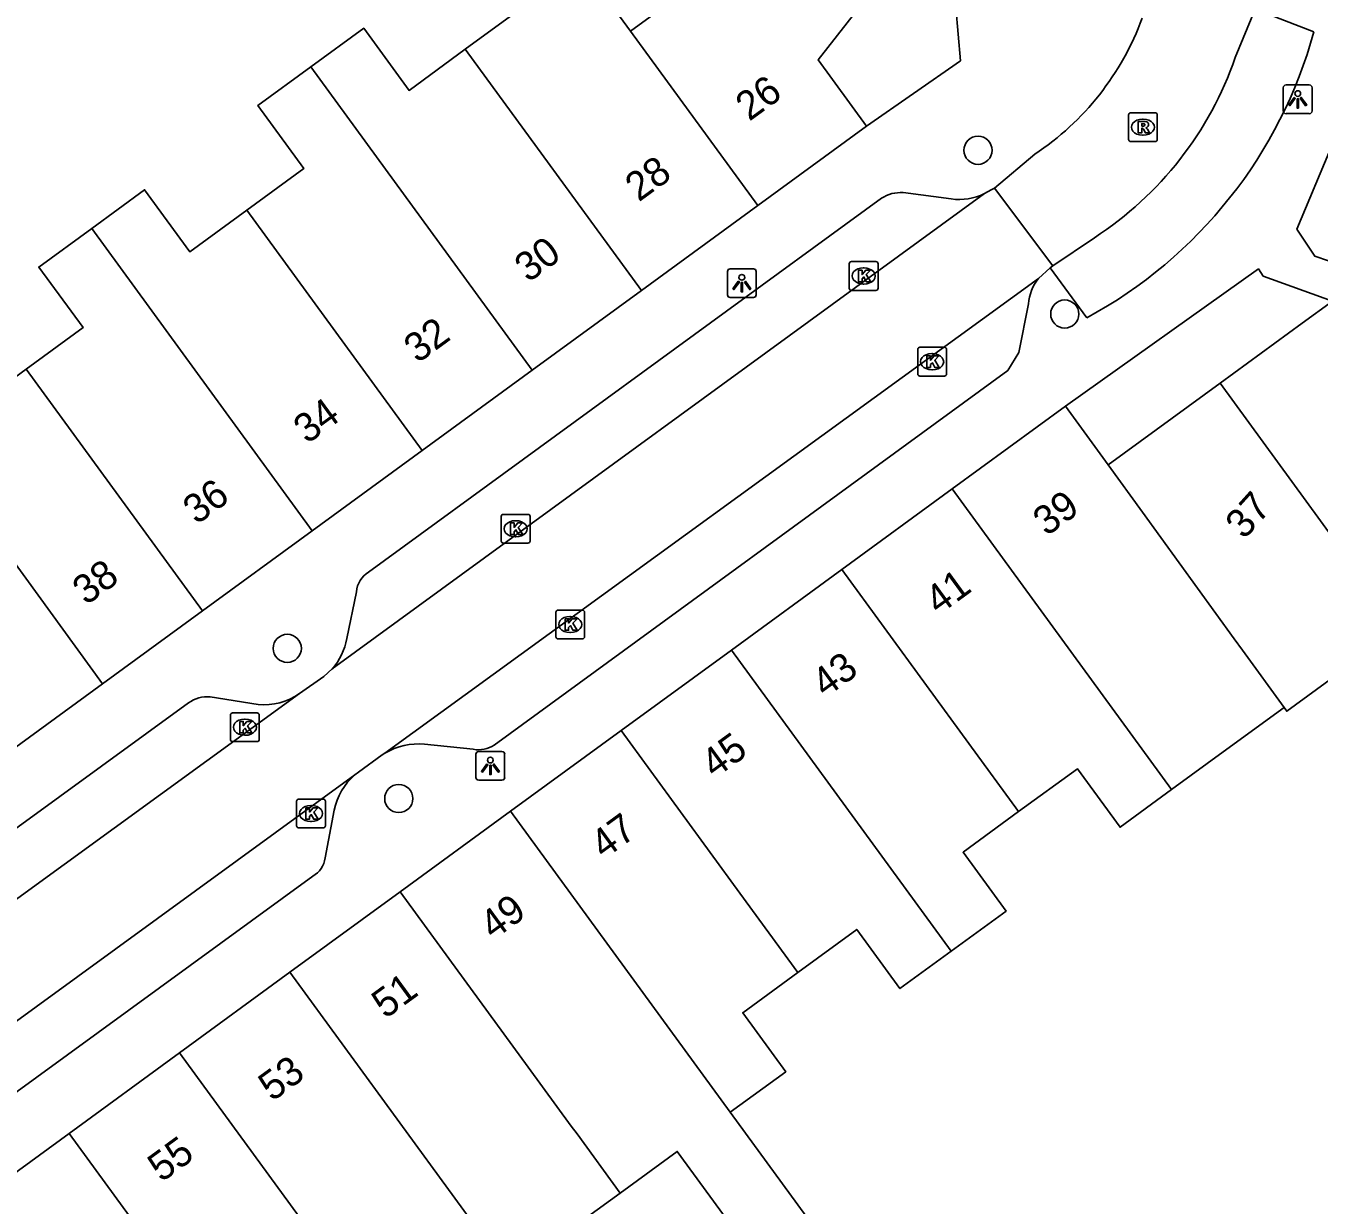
# Model space of a CAD drawing. Extents: x 159822 to 160765, y 380693 to 381634.
# Drawn here: x 160006.47 to 160051.39, y 381310.61 to 381351.57 of the extents above; entities that cross this region are included whole.
import ezdxf

# ---------------------------------------------------------------- set-up
doc = ezdxf.new("R2010")
doc.units = 0
for name, color, linetype in [('IMGEO_Boom', 7, 'Continuous'), ('IMGEO_Kolk', 7, 'Continuous'), ('IMGEO_Lichtpunt', 7, 'Continuous'), ('IMGEO_Pand', 7, 'Continuous'), ('IMGEO_Pand_nummerreeks', 7, 'Continuous'), ('IMGEO_Rijbaan_lokaal_open', 7, 'Continuous'), ('IMGEO_Rioolput', 7, 'Continuous'), ('IMGEO_Voetpad_open', 7, 'Continuous')]:
    doc.layers.add(name, color=color, linetype=linetype)

msp = doc.modelspace()

# ---------------------------------------------------------------- linework, layer by layer
at = {"layer": 'IMGEO_Boom'}
for centre in [(160039.538, 381347.249), (160042.551, 381341.561), (160015.549, 381329.949), (160019.421, 381324.733)]:
    msp.add_circle(centre, 0.489, dxfattribs=at)
at = {"layer": 'IMGEO_Kolk'}
for p, q in [((160035.066, 381342.457), (160035.066, 381343.309)), ((160035.141, 381343.383), (160035.993, 381343.383)), ((160035.554, 381343.163), (160035.579, 381343.163)), ((160036.067, 381343.309), (160036.067, 381342.457)), ((160035.577, 381342.603), (160035.552, 381342.603)), ((160035.993, 381342.383), (160035.141, 381342.383)), ((160037.444, 381339.479), (160037.444, 381340.331)), ((160037.519, 381340.405), (160038.371, 381340.405)), ((160038.445, 381340.331), (160038.445, 381339.479)), ((160037.932, 381340.185), (160037.957, 381340.185)), ((160037.955, 381339.625), (160037.93, 381339.625)), ((160038.371, 381339.405), (160037.519, 381339.405)), ((160022.981, 381333.677), (160022.981, 381334.529)), ((160023.056, 381334.603), (160023.908, 381334.603)), ((160023.982, 381334.529), (160023.982, 381333.677)), ((160023.469, 381334.383), (160023.494, 381334.383)), ((160023.908, 381333.603), (160023.056, 381333.603)), ((160023.492, 381333.823), (160023.467, 381333.823)), ((160024.875, 381330.351), (160024.875, 381331.203)), ((160024.95, 381331.277), (160025.802, 381331.277)), ((160025.363, 381331.057), (160025.388, 381331.057)), ((160025.876, 381331.203), (160025.876, 381330.351)), ((160025.386, 381330.497), (160025.361, 381330.497)), ((160025.802, 381330.277), (160024.95, 381330.277)), ((160013.576, 381326.783), (160013.576, 381327.635)), ((160013.651, 381327.709), (160014.503, 381327.709)), ((160014.064, 381327.489), (160014.089, 381327.489)), ((160014.577, 381327.635), (160014.577, 381326.783)), ((160014.087, 381326.929), (160014.062, 381326.929)), ((160014.503, 381326.709), (160013.651, 381326.709)), ((160015.874, 381323.786), (160015.874, 381324.638)), ((160015.949, 381324.712), (160016.801, 381324.712)), ((160016.875, 381324.638), (160016.875, 381323.786)), ((160016.362, 381324.492), (160016.387, 381324.492)), ((160016.385, 381323.932), (160016.36, 381323.932)), ((160016.801, 381323.712), (160015.949, 381323.712))]:
    msp.add_line(p, q, dxfattribs=at)
for points in [[(160035.066, 381342.457), (160035.066, 381343.309)], [(160035.141, 381343.383), (160035.993, 381343.383)], [(160035.387, 381343.083), (160035.51, 381343.083), (160035.51, 381342.932), (160035.64, 381343.083), (160035.804, 381343.083), (160035.658, 381342.932), (160035.811, 381342.683), (160035.659, 381342.683), (160035.574, 381342.847), (160035.51, 381342.78), (160035.51, 381342.683), (160035.387, 381342.683), (160035.387, 381343.083)], [(160036.067, 381343.309), (160036.067, 381342.457)], [(160035.993, 381342.383), (160035.141, 381342.383)], [(160037.444, 381339.479), (160037.444, 381340.331)], [(160037.519, 381340.405), (160038.371, 381340.405)], [(160038.445, 381340.331), (160038.445, 381339.479)], [(160037.765, 381340.105), (160037.888, 381340.105), (160037.888, 381339.954), (160038.018, 381340.105), (160038.182, 381340.105), (160038.036, 381339.954), (160038.189, 381339.705), (160038.037, 381339.705), (160037.952, 381339.869), (160037.888, 381339.802), (160037.888, 381339.705), (160037.765, 381339.705), (160037.765, 381340.105)], [(160038.371, 381339.405), (160037.519, 381339.405)], [(160022.981, 381333.677), (160022.981, 381334.529)], [(160023.056, 381334.603), (160023.908, 381334.603)], [(160023.982, 381334.529), (160023.982, 381333.677)], [(160023.302, 381334.303), (160023.425, 381334.303), (160023.425, 381334.152), (160023.555, 381334.303), (160023.719, 381334.303), (160023.573, 381334.152), (160023.726, 381333.903), (160023.574, 381333.903), (160023.489, 381334.067), (160023.425, 381334), (160023.425, 381333.903), (160023.302, 381333.903), (160023.302, 381334.303)], [(160023.908, 381333.603), (160023.056, 381333.603)], [(160024.875, 381330.351), (160024.875, 381331.203)], [(160024.95, 381331.277), (160025.802, 381331.277)], [(160025.196, 381330.977), (160025.319, 381330.977), (160025.319, 381330.826), (160025.449, 381330.977), (160025.613, 381330.977), (160025.467, 381330.826), (160025.62, 381330.577), (160025.468, 381330.577), (160025.383, 381330.741), (160025.319, 381330.674), (160025.319, 381330.577), (160025.196, 381330.577), (160025.196, 381330.977)], [(160025.876, 381331.203), (160025.876, 381330.351)], [(160025.802, 381330.277), (160024.95, 381330.277)], [(160013.576, 381326.783), (160013.576, 381327.635)], [(160013.651, 381327.709), (160014.503, 381327.709)], [(160013.897, 381327.409), (160014.02, 381327.409), (160014.02, 381327.258), (160014.15, 381327.409), (160014.314, 381327.409), (160014.168, 381327.258), (160014.321, 381327.009), (160014.169, 381327.009), (160014.084, 381327.173), (160014.02, 381327.106), (160014.02, 381327.009), (160013.897, 381327.009), (160013.897, 381327.409)], [(160014.577, 381327.635), (160014.577, 381326.783)], [(160014.503, 381326.709), (160013.651, 381326.709)], [(160015.874, 381323.786), (160015.874, 381324.638)], [(160015.949, 381324.712), (160016.801, 381324.712)], [(160016.875, 381324.638), (160016.875, 381323.786)], [(160016.195, 381324.412), (160016.318, 381324.412), (160016.318, 381324.261), (160016.448, 381324.412), (160016.612, 381324.412), (160016.466, 381324.261), (160016.619, 381324.012), (160016.467, 381324.012), (160016.382, 381324.176), (160016.318, 381324.109), (160016.318, 381324.012), (160016.195, 381324.012), (160016.195, 381324.412)], [(160016.801, 381323.712), (160015.949, 381323.712)]]:
    msp.add_lwpolyline(points, dxfattribs=at)
for centre, start, end in [((160035.143, 381343.307), 91.552, 178.448), ((160035.143, 381343.307), 91.552, 178.448), ((160035.991, 381343.307), 1.552, 88.448), ((160035.991, 381343.307), 1.552, 88.448), ((160035.143, 381342.459), 181.552, 268.448), ((160035.143, 381342.459), 181.552, 268.448), ((160035.991, 381342.459), 271.552, 358.448), ((160035.991, 381342.459), 271.552, 358.448), ((160037.521, 381340.329), 91.552, 178.448), ((160037.521, 381340.329), 91.552, 178.448), ((160038.369, 381340.329), 1.552, 88.448), ((160038.369, 381340.329), 1.552, 88.448), ((160037.521, 381339.481), 181.552, 268.448), ((160037.521, 381339.481), 181.552, 268.448), ((160038.369, 381339.481), 271.552, 358.448), ((160038.369, 381339.481), 271.552, 358.448), ((160023.058, 381334.527), 91.552, 178.448), ((160023.058, 381334.527), 91.552, 178.448), ((160023.906, 381334.527), 1.552, 88.448), ((160023.906, 381334.527), 1.552, 88.448), ((160023.058, 381333.679), 181.552, 268.448), ((160023.058, 381333.679), 181.552, 268.448), ((160023.906, 381333.679), 271.552, 358.448), ((160023.906, 381333.679), 271.552, 358.448), ((160024.952, 381331.201), 91.552, 178.448), ((160024.952, 381331.201), 91.552, 178.448), ((160025.8, 381331.201), 1.552, 88.448), ((160025.8, 381331.201), 1.552, 88.448), ((160024.952, 381330.353), 181.552, 268.448), ((160024.952, 381330.353), 181.552, 268.448), ((160025.8, 381330.353), 271.552, 358.448), ((160025.8, 381330.353), 271.552, 358.448), ((160013.653, 381327.633), 91.552, 178.448), ((160013.653, 381327.633), 91.552, 178.448), ((160014.501, 381327.633), 1.552, 88.448), ((160014.501, 381327.633), 1.552, 88.448), ((160013.653, 381326.785), 181.552, 268.448), ((160013.653, 381326.785), 181.552, 268.448), ((160014.501, 381326.785), 271.552, 358.448), ((160014.501, 381326.785), 271.552, 358.448), ((160015.951, 381324.636), 91.552, 178.448), ((160015.951, 381324.636), 91.552, 178.448), ((160016.799, 381324.636), 1.552, 88.448), ((160016.799, 381324.636), 1.552, 88.448), ((160015.951, 381323.788), 181.552, 268.448), ((160015.951, 381323.788), 181.552, 268.448), ((160016.799, 381323.788), 271.552, 358.448), ((160016.799, 381323.788), 271.552, 358.448)]:
    msp.add_arc(centre, 0.0765, start, end, dxfattribs=at)
for centre, major_axis, ratio, start_param, end_param in [((160035.553, 381342.883), (-0.387, 0.002), 0.722429, 4.712389, 7.853982), ((160035.578, 381342.883), (-0.39, 0.002), 0.717154, 1.570796, 4.712389), ((160037.931, 381339.905), (-0.387, 0.002), 0.722429, 4.712389, 7.853982), ((160037.956, 381339.905), (-0.39, 0.002), 0.717154, 1.570796, 4.712389), ((160023.468, 381334.103), (-0.387, 0.002), 0.722429, 4.712389, 7.853982), ((160023.493, 381334.103), (-0.39, 0.002), 0.717154, 1.570796, 4.712389), ((160025.362, 381330.777), (-0.387, 0.002), 0.722429, 4.712389, 7.853982), ((160025.387, 381330.777), (-0.39, 0.002), 0.717154, 1.570796, 4.712389), ((160014.063, 381327.209), (-0.387, 0.002), 0.722429, 4.712389, 7.853982), ((160014.088, 381327.209), (-0.39, 0.002), 0.717154, 1.570796, 4.712389), ((160016.361, 381324.212), (-0.387, 0.002), 0.722429, 4.712389, 7.853982), ((160016.386, 381324.212), (-0.39, 0.002), 0.717154, 1.570796, 4.712389)]:
    msp.add_ellipse(centre, major_axis=major_axis, ratio=ratio, start_param=start_param, end_param=end_param, dxfattribs=at)
at = {"layer": 'IMGEO_Lichtpunt'}
for p, q in [((160050.142, 381349.421), (160050.142, 381348.614)), ((160050.142, 381349.421), (160050.142, 381348.614)), ((160051.044, 381349.516), (160050.236, 381349.516)), ((160051.044, 381349.516), (160050.236, 381349.516)), ((160051.138, 381348.614), (160051.138, 381349.421)), ((160051.138, 381348.614), (160051.138, 381349.421)), ((160050.236, 381348.52), (160051.044, 381348.52)), ((160050.236, 381348.52), (160051.044, 381348.52)), ((160030.837, 381343.037), (160030.837, 381342.23)), ((160030.837, 381343.037), (160030.837, 381342.23)), ((160031.739, 381343.132), (160030.931, 381343.132)), ((160031.739, 381343.132), (160030.931, 381343.132)), ((160031.833, 381342.23), (160031.833, 381343.037)), ((160031.833, 381342.23), (160031.833, 381343.037)), ((160030.931, 381342.136), (160031.739, 381342.136)), ((160030.931, 381342.136), (160031.739, 381342.136)), ((160022.103, 381326.272), (160022.103, 381325.465)), ((160022.103, 381326.272), (160022.103, 381325.465)), ((160023.005, 381326.367), (160022.197, 381326.367)), ((160023.005, 381326.367), (160022.197, 381326.367)), ((160023.099, 381325.465), (160023.099, 381326.272)), ((160023.099, 381325.465), (160023.099, 381326.272)), ((160022.197, 381325.371), (160023.005, 381325.371)), ((160022.197, 381325.371), (160023.005, 381325.371))]:
    msp.add_line(p, q, dxfattribs=at)
for points in [[(160050.516, 381349.085), (160050.555, 381349.057), (160050.367, 381348.795), (160050.329, 381348.822), (160050.516, 381349.085)], [(160050.618, 381349.037), (160050.665, 381349.037), (160050.665, 381348.715), (160050.618, 381348.715), (160050.618, 381349.037)], [(160050.728, 381349.057), (160050.766, 381349.084), (160050.953, 381348.822), (160050.914, 381348.794), (160050.728, 381349.057)], [(160031.211, 381342.701), (160031.25, 381342.673), (160031.062, 381342.411), (160031.024, 381342.438), (160031.211, 381342.701)], [(160031.313, 381342.653), (160031.36, 381342.653), (160031.36, 381342.331), (160031.313, 381342.331), (160031.313, 381342.653)], [(160031.423, 381342.673), (160031.461, 381342.7), (160031.648, 381342.438), (160031.609, 381342.41), (160031.423, 381342.673)], [(160022.477, 381325.936), (160022.516, 381325.908), (160022.328, 381325.646), (160022.29, 381325.673), (160022.477, 381325.936)], [(160022.579, 381325.888), (160022.626, 381325.888), (160022.626, 381325.566), (160022.579, 381325.566), (160022.579, 381325.888)], [(160022.689, 381325.908), (160022.727, 381325.935), (160022.914, 381325.673), (160022.875, 381325.645), (160022.689, 381325.908)]]:
    msp.add_lwpolyline(points, dxfattribs=at)
for centre in [(160050.641, 381349.219), (160031.336, 381342.835), (160022.602, 381326.07)]:
    msp.add_circle(centre, 0.0994, dxfattribs=at)
for centre, start, end in [((160050.236, 381349.421), 90, 180), ((160050.236, 381349.421), 90, 180), ((160051.044, 381349.421), 0, 90), ((160051.044, 381349.421), 0, 90), ((160050.236, 381348.614), 180, 270), ((160050.236, 381348.614), 180, 270), ((160051.044, 381348.614), 270, 0), ((160051.044, 381348.614), 270, 360), ((160030.931, 381343.037), 90, 180), ((160030.931, 381343.037), 90, 180), ((160031.739, 381343.037), 0, 90), ((160031.739, 381343.037), 0, 90), ((160030.931, 381342.23), 180, 270), ((160030.931, 381342.23), 180, 270), ((160031.739, 381342.23), 270, 0), ((160031.739, 381342.23), 270, 360), ((160022.197, 381326.272), 90, 180), ((160022.197, 381326.272), 90, 180), ((160023.005, 381326.272), 0, 90), ((160023.005, 381326.272), 0, 90), ((160022.197, 381325.465), 180, 270), ((160022.197, 381325.465), 180, 270), ((160023.005, 381325.465), 270, 0), ((160023.005, 381325.465), 270, 360)]:
    msp.add_arc(centre, 0.0946, start, end, dxfattribs=at)
at = {"layer": 'IMGEO_Pand'}
for points in [[(160027.467, 381351.387), (160031.335, 381354.211), (160033.164, 381356.557)], [(160021.732, 381350.755), (160023.683, 381352.18), (160022.128, 381354.309), (160024.219, 381355.836), (160027.467, 381351.387)], [(160036.671, 381353.824), (160033.991, 381350.384), (160035.667, 381348.09)], [(160021.732, 381350.755), (160019.781, 381349.33), (160018.206, 381351.488), (160016.367, 381350.146)], [(160027.467, 381351.387), (160031.888, 381345.331)], [(160027.848, 381342.381), (160021.732, 381350.755)], [(160014.145, 381345.171), (160016.126, 381346.617), (160014.529, 381348.804), (160016.367, 381350.146)], [(160016.367, 381350.146), (160024.056, 381339.612)], [(160035.667, 381348.09), (160031.888, 381345.331)], [(160008.756, 381344.535), (160010.594, 381345.876), (160012.164, 381343.725), (160014.145, 381345.171)], [(160031.888, 381345.331), (160027.848, 381342.381)], [(160020.237, 381336.824), (160014.145, 381345.171)], [(160008.756, 381344.535), (160006.919, 381343.194), (160008.455, 381341.09), (160006.477, 381339.646)], [(160016.419, 381334.035), (160008.756, 381344.535)], [(160024.056, 381339.612), (160027.848, 381342.381)], [(160051.849, 381342.011), (160050.798, 381341.244), (160047.948, 381339.164)], [(160006.477, 381339.646), (160004.5, 381338.203), (160002.944, 381340.334), (160001.472, 381339.264)], [(160012.606, 381331.251), (160006.477, 381339.646)], [(160024.056, 381339.612), (160020.237, 381336.824)], [(160001.472, 381339.264), (160009.135, 381328.717)], [(160047.948, 381339.164), (160044.062, 381336.328)], [(160055.586, 381328.689), (160055.512, 381328.791), (160047.948, 381339.164)], [(160042.579, 381338.36), (160038.642, 381335.486)], [(160044.062, 381336.328), (160042.579, 381338.36)], [(160016.419, 381334.035), (160020.237, 381336.824)], [(160050.169, 381327.896), (160048.724, 381329.89), (160048.437, 381330.285), (160045.249, 381334.68), (160044.062, 381336.328)], [(160038.642, 381335.486), (160034.808, 381332.688)], [(160038.642, 381335.486), (160046.262, 381325.044)], [(160012.606, 381331.251), (160016.419, 381334.035)], [(160034.808, 381332.688), (160030.974, 381329.89)], [(160040.947, 381324.277), (160039.223, 381326.639), (160034.808, 381332.688)], [(160009.135, 381328.717), (160012.606, 381331.251)], [(160027.141, 381327.093), (160030.974, 381329.89)], [(160030.974, 381329.89), (160038.608, 381319.431)], [(160050.169, 381327.896), (160050.263, 381327.767), (160052.323, 381329.27), (160053.733, 381327.337), (160055.586, 381328.689)], [(160004.957, 381325.667), (160009.135, 381328.717)], [(160046.262, 381325.044), (160048.18, 381326.444), (160050.169, 381327.896)], [(160027.141, 381327.093), (160023.307, 381324.295)], [(160033.275, 381318.687), (160031.264, 381321.443), (160027.141, 381327.093)], [(160046.262, 381325.044), (160044.472, 381323.738), (160042.99, 381325.769), (160040.947, 381324.277)], [(160023.307, 381324.295), (160019.473, 381321.497)], [(160030.936, 381313.84), (160023.307, 381324.295)], [(160038.608, 381319.431), (160040.512, 381320.821), (160039.018, 381322.869), (160040.947, 381324.277)], [(160019.473, 381321.497), (160015.639, 381318.698)], [(160027.112, 381311.031), (160025.613, 381313.084), (160025.414, 381313.356), (160023.918, 381315.406), (160019.473, 381321.497)], [(160038.608, 381319.431), (160036.826, 381318.131), (160035.327, 381320.185), (160033.275, 381318.687)], [(160015.639, 381318.698), (160011.806, 381315.901)], [(160015.639, 381318.698), (160023.278, 381308.232), (160025.935, 381304.592)], [(160030.936, 381313.84), (160032.862, 381315.245), (160031.367, 381317.294), (160033.275, 381318.687)], [(160011.806, 381315.901), (160007.973, 381313.103)], [(160017.923, 381307.519), (160016.189, 381309.895), (160011.806, 381315.901)], [(160027.112, 381311.031), (160029.091, 381312.475), (160032.714, 381307.513), (160034.316, 381308.682), (160034.5, 381308.817), (160034.566, 381308.865), (160030.936, 381313.84)], [(160007.973, 381313.103), (160004.139, 381310.305)], [(160007.973, 381313.103), (160015.606, 381302.643)], [(160025.935, 381304.592), (160026.041, 381304.67), (160026.303, 381304.861), (160027.839, 381305.982), (160025.182, 381309.622), (160027.112, 381311.031)]]:
    msp.add_lwpolyline(points, dxfattribs=at)
at = {"layer": 'IMGEO_Rijbaan_lokaal_open'}
for points in [[(160049.167, 381352.154), (160048.471, 381350.471)], [(160041.508, 381347.109), (160040.114, 381345.931)], [(160017.107, 381329.232), (160039.766, 381345.742)], [(160039.766, 381345.742), (160039.995, 381345.875), (160040.114, 381345.931)], [(160040.114, 381345.931), (160042.137, 381343.23)], [(160043.581, 381344.211), (160042.137, 381343.23)], [(160042.049, 381343.165), (160041.64, 381342.795)], [(160042.137, 381343.23), (160042.049, 381343.165)], [(160041.64, 381342.795), (160018.937, 381326.306)], [(160015.971, 381328.377), (160016.824, 381328.969), (160017.107, 381329.232)], [(159988.276, 381308.413), (159988.356, 381308.32), (160015.971, 381328.377)], [(160018.937, 381326.306), (160018.848, 381326.249), (160018.017, 381325.646), (160017.899, 381325.552)], [(160017.899, 381325.552), (159990.347, 381305.507), (159990.451, 381305.346)]]:
    msp.add_lwpolyline(points, dxfattribs=at)
for centre, radius, start, end in [((160036.163, 381355.164), 9.667, 303.5665, 339.8948), ((160036.937, 381354.441), 12.198, 303.0026, 341.007)]:
    msp.add_arc(centre, radius, start, end, dxfattribs=at)
at = {"layer": 'IMGEO_Rioolput'}
for p, q in [((160044.764, 381347.625), (160044.764, 381348.477)), ((160044.839, 381348.551), (160045.691, 381348.551)), ((160045.765, 381348.477), (160045.765, 381347.625)), ((160045.252, 381348.331), (160045.277, 381348.331)), ((160045.691, 381347.551), (160044.839, 381347.551)), ((160045.275, 381347.771), (160045.25, 381347.771))]:
    msp.add_line(p, q, dxfattribs=at)
for points in [[(160044.764, 381347.625), (160044.764, 381348.477)], [(160044.839, 381348.551), (160045.691, 381348.551)], [(160045.765, 381348.477), (160045.765, 381347.625)], [(160045.353, 381348.249), (160045.101, 381348.251), (160045.101, 381347.851)], [(160045.101, 381347.851), (160045.225, 381347.851), (160045.225, 381348.013), (160045.236, 381348.013)], [(160045.279, 381348.17), (160045.225, 381348.17), (160045.225, 381348.089)], [(160045.225, 381348.089), (160045.277, 381348.089)], [(160045.283, 381347.984), (160045.354, 381347.851), (160045.494, 381347.851), (160045.429, 381347.977)], [(160045.691, 381347.551), (160044.839, 381347.551)]]:
    msp.add_lwpolyline(points, dxfattribs=at)
for centre, radius, start, end in [((160044.841, 381348.475), 0.0765, 91.552, 178.448), ((160044.841, 381348.475), 0.0765, 91.552, 178.448), ((160045.689, 381348.475), 0.0765, 1.552, 88.448), ((160045.689, 381348.475), 0.0765, 1.552, 88.448), ((160045.235, 381347.96), 0.0533, 26.0293, 88.6989), ((160045.261, 381348.278), 0.19, 274.7715, 282.9687), ((160045.285, 381348.074), 0.0964, 77.0061, 93.1865), ((160045.299, 381348.131), 0.0378, 276.6634, 79.6772), ((160045.352, 381348.139), 0.109, 350.3612, 89.416), ((160045.35, 381348.139), 0.112, 277.5842, 350.9817), ((160045.334, 381347.924), 0.108, 29.5134, 73.7905), ((160044.841, 381347.627), 0.0765, 181.552, 268.448), ((160044.841, 381347.627), 0.0765, 181.552, 268.448), ((160045.689, 381347.627), 0.0765, 271.552, 358.448), ((160045.689, 381347.627), 0.0765, 271.552, 358.448)]:
    msp.add_arc(centre, radius, start, end, dxfattribs=at)
for centre, major_axis, ratio, start_param, end_param in [((160045.251, 381348.051), (-0.387, 0.002), 0.722429, 4.712389, 7.853982), ((160045.276, 381348.051), (-0.39, 0.002), 0.717154, 1.570796, 4.712389)]:
    msp.add_ellipse(centre, major_axis=major_axis, ratio=ratio, start_param=start_param, end_param=end_param, dxfattribs=at)
at = {"layer": 'IMGEO_Voetpad_open'}
for points in [[(160035.667, 381348.09), (160038.934, 381350.359), (160038.773, 381352.204), (160036.769, 381353.793)], [(160054.093, 381352.833), (160050.607, 381344.513), (160051.233, 381343.569), (160052.664, 381343.089)], [(160051.204, 381351.366), (160049.167, 381352.154)], [(160038.607, 381345.559), (160036.938, 381345.778)], [(160036.192, 381345.582), (160018.371, 381332.597)], [(160042.049, 381343.165), (160043.321, 381341.431)], [(160042.579, 381338.36), (160049.274, 381343.128), (160049.447, 381342.874), (160051.849, 381342.011)], [(160041.286, 381341.91), (160040.956, 381340.229), (160040.579, 381339.605), (160022.736, 381326.589)], [(160017.957, 381331.91), (160017.613, 381330.288)], [(160012.87, 381328.268), (160014.537, 381328.002)], [(159989.891, 381311.884), (160012.121, 381328.054)], [(160022.009, 381326.442), (160020.319, 381326.621)], [(160017.18, 381324.331), (160016.867, 381322.671)], [(160016.438, 381322.033), (159994.185, 381305.844)]]:
    msp.add_lwpolyline(points, dxfattribs=at)
for centre, radius, start, end in [((160035.619, 381355.637), 16.16, 298.4648, 344.6742), ((160036.857, 381344.57), 1.211, 86.1471, 123.2946), ((160038.894, 381347.505), 1.967, 261.6207, 296.3245), ((160042.933, 381341.765), 1.653, 141.4417, 174.9554), ((160018.798, 381331.871), 0.842, 120.4906, 177.3614), ((160015.54, 381330.632), 2.102, 318.2236, 350.572), ((160012.795, 381327.114), 1.156, 86.2581, 125.6327), ((160014.768, 381330.048), 2.059, 263.5571, 305.7529), ((160020.104, 381324.376), 2.255, 84.5221, 121.1581), ((160022.188, 381327.43), 1.004, 259.7564, 303.1058), ((160019.305, 381323.902), 2.168, 130.4349, 168.5807), ((160015.957, 381322.82), 0.923, 301.4584, 350.7068)]:
    msp.add_arc(centre, radius, start, end, dxfattribs=at)

# ---------------------------------------------------------------- texts
at = {"layer": 'IMGEO_Pand_nummerreeks'}
for s, rotation, p in [('26', 36.1342, (160031.595, 381348.236)), ('28', 36.1342, (160027.758, 381345.435)), ('30', 36.1342, (160023.92, 381342.633)), ('32', 36.1342, (160020.076, 381339.827)), ('34', 36.1342, (160016.241, 381337.026)), ('36', 36.1342, (160012.402, 381334.223)), ('37', 48.0024, (160048.783, 381333.703)), ('39', 36.125, (160041.923, 381333.821)), ('38', 36.1342, (160008.566, 381331.423)), ('41', 36.1236, (160038.172, 381331.082)), ('43', 36.1236, (160034.237, 381328.21)), ('45', 36.1236, (160030.394, 381325.406)), ('47', 36.1236, (160026.551, 381322.601)), ('49', 36.125, (160022.708, 381319.797)), ('51', 36.125, (160018.957, 381317.059)), ('53', 36.125, (160015.022, 381314.187)), ('55', 36.1236, (160011.179, 381311.382))]:
    msp.add_text(s, height=1, rotation=rotation, dxfattribs=at).set_placement(p)

doc.saveas('drawing.dxf')
